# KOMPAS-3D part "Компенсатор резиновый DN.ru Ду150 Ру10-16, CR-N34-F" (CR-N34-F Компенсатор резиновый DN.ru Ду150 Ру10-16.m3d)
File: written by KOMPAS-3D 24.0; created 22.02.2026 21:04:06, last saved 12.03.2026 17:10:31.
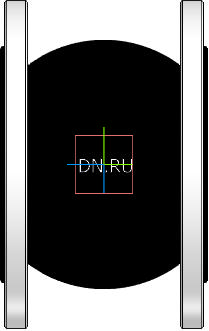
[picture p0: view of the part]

Document properties: Автор: DN.RU; Полное имя файла: CR-N34-F Компенсатор резиновый DN.ru Ду150 Ру10-16.cdw

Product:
- Body: Твердое тело2  | qty 1
    Масса: 29.199535
- Part/product: Компенсатор резиновый DN.ru Ду150 Ру10-16  | designation CR-N34-F
    Масса: 15
    Раздел спецификации: Прочие изделия
    Форматы листов документа: A2
    Комментарий: D140-02094
    Примечание: D140-02094
    additional columns: Типовые

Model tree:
1. Твердое тело2  (labels: Твердое тело2)

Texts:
  CR-N34-F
